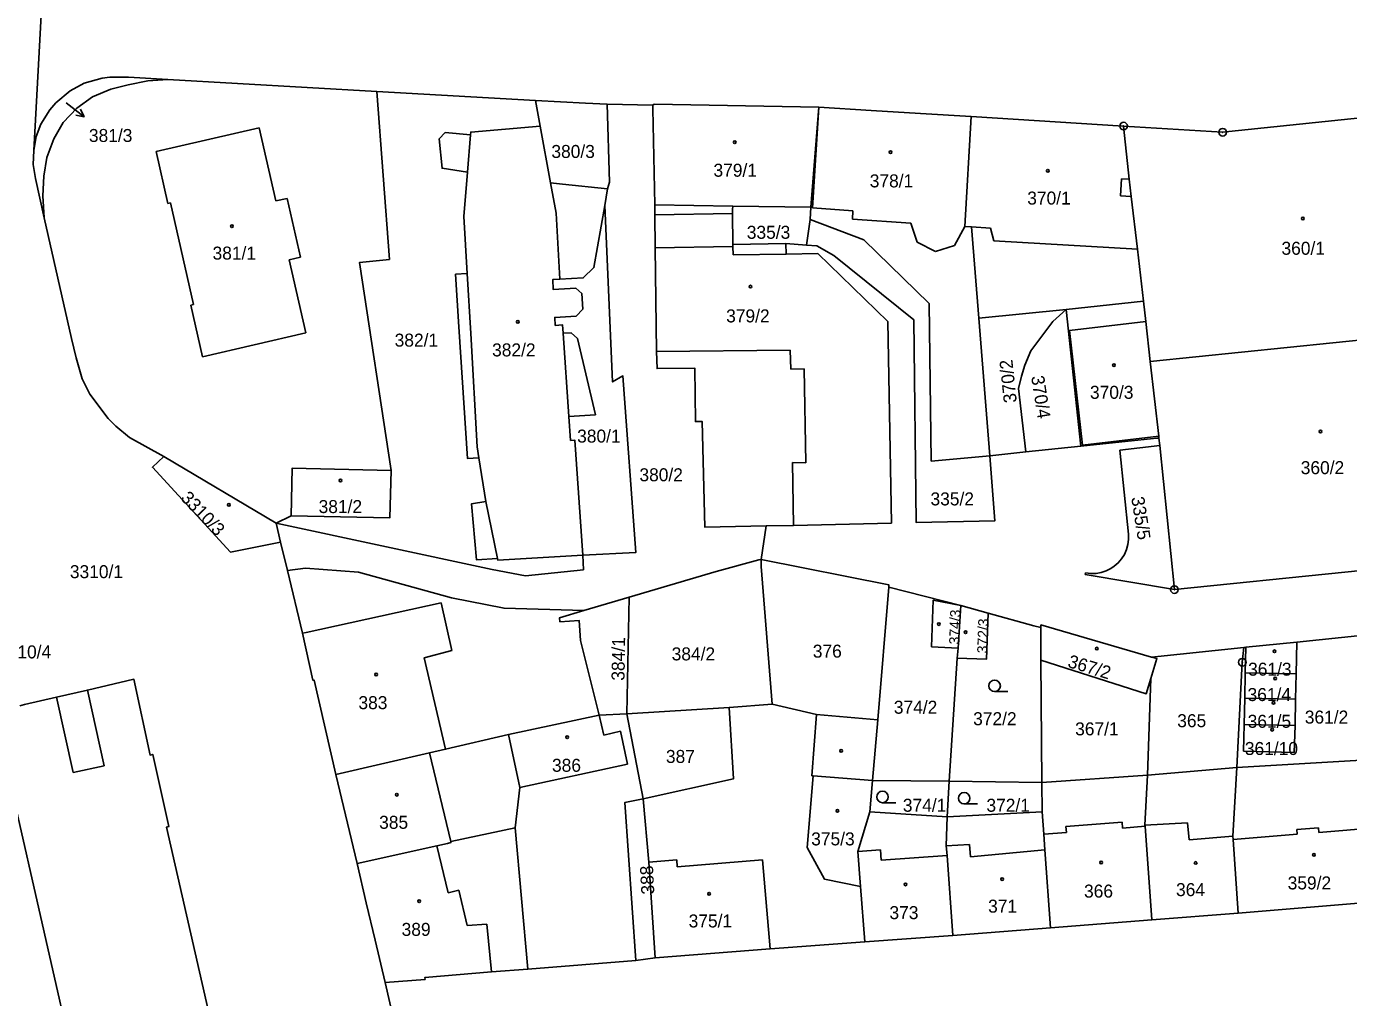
# Model space of a CAD drawing. Extents: x -733394 to -722299, y -1082822 to -1075049.
# Drawn here: x -728810.6 to -728637.6, y -1079423 to -1079295.9 of the extents above; entities that cross this region are included whole.
import ezdxf

# ---------------------------------------------------------------- set-up
doc = ezdxf.new("R2010")
doc.units = 0
for name, color, linetype in [('Hranice parcel', 7, 'Continuous'), ('Parcelní čísla', 7, 'Continuous'), ('Pop  PČ popisy', 7, 'Continuous'), ('Vnitřní kresba', 7, 'Continuous'), ('Značky bodu BP', 7, 'Continuous'), ('Značky budov', 7, 'Continuous'), ('Značky kultur', 7, 'Continuous')]:
    doc.layers.add(name, color=color, linetype=linetype)

msp = doc.modelspace()

# ---------------------------------------------------------------- linework, layer by layer
at = {"layer": 'Hranice parcel'}
for p, q in [((-728808.04, -1079282.72), (-728809.66, -1079312.11)), ((-728764.77, -1079304.39), (-728792.13, -1079302.84)), ((-728744.02, -1079305.57), (-728764.77, -1079304.39)), ((-728743.4, -1079308.95), (-728744.02, -1079305.57)), ((-728728.64, -1079306.19), (-728734.61, -1079306.05)), ((-728706.94, -1079306.46), (-728707.99, -1079319.55)), ((-728667.05, -1079308.93), (-728686.99, -1079307.69)), ((-728734.56, -1079317.13), (-728734.92, -1079319.33)), ((-728728.4, -1079319.25), (-728718.19, -1079319.41)), ((-728707.99, -1079319.55), (-728718.19, -1079319.41)), ((-728708.05, -1079321.14), (-728708.55, -1079324.51)), ((-728708.05, -1079321.14), (-728707.99, -1079319.55)), ((-728708.55, -1079324.51), (-728711.23, -1079324.31)), ((-728685.98, -1079334.08), (-728674.55, -1079332.94)), ((-728674.55, -1079332.94), (-728664.45, -1079331.86)), ((-728674.55, -1079332.94), (-728672.62, -1079350.8)), ((-728685.98, -1079334.08), (-728684.56, -1079352.08)), ((-728663.56, -1079339.73), (-728618.85, -1079335.2)), ((-728662.32, -1079350.72), (-728662.42, -1079349.75)), ((-728792.64, -1079352.18), (-728777.92, -1079360.9)), ((-728679.82, -1079351.54), (-728684.56, -1079352.08)), ((-728672.62, -1079350.8), (-728679.82, -1079351.54)), ((-728662.32, -1079350.72), (-728660.39, -1079369.59)), ((-728777.92, -1079360.9), (-728775.98, -1079359.93)), ((-728777.92, -1079360.9), (-728777.39, -1079363.36)), ((-728713.81, -1079361.26), (-728714.46, -1079365.65)), ((-728777.39, -1079363.36), (-728776.44, -1079367.09)), ((-728697.78, -1079369.26), (-728699.2, -1079386.62)), ((-728697.78, -1079369.26), (-728688.35, -1079371.68)), ((-728737.67, -1079372.33), (-728731.76, -1079370.58)), ((-728732.03, -1079385.83), (-728731.76, -1079370.58)), ((-728688.35, -1079371.68), (-728688.71, -1079377.25)), ((-728688.35, -1079371.68), (-728684.77, -1079372.66)), ((-728677.85, -1079378.84), (-728677.88, -1079374.54)), ((-728651.03, -1079377.14), (-728644.36, -1079376.45)), ((-728644.36, -1079376.45), (-728644.46, -1079380.63)), ((-728644.36, -1079376.45), (-728635.6, -1079375.55)), ((-728688.8, -1079378.56), (-728688.71, -1079377.25)), ((-728663.37, -1079378.41), (-728651.31, -1079377.17)), ((-728651.31, -1079377.17), (-728651.03, -1079377.14)), ((-728651.12, -1079380.48), (-728651.03, -1079377.14)), ((-728688.8, -1079378.56), (-728689.85, -1079394.67)), ((-728677.73, -1079394.81), (-728677.85, -1079378.84)), ((-728663.47, -1079381.21), (-728663.9, -1079393.89)), ((-728651.19, -1079383.78), (-728651.12, -1079380.48)), ((-728651.12, -1079380.48), (-728644.46, -1079380.63)), ((-728644.46, -1079380.63), (-728644.53, -1079383.93)), ((-728732.03, -1079385.83), (-728718.64, -1079385.03)), ((-728713.04, -1079384.6), (-728718.64, -1079385.03)), ((-728651.27, -1079387.23), (-728651.19, -1079383.78)), ((-728651.19, -1079383.78), (-728644.53, -1079383.93)), ((-728644.53, -1079383.93), (-728644.61, -1079387.38)), ((-728747.54, -1079388.54), (-728735.68, -1079386.04)), ((-728735.68, -1079386.04), (-728732.03, -1079385.83)), ((-728729.91, -1079396.97), (-728732.03, -1079385.83)), ((-728699.2, -1079386.62), (-728699.88, -1079394.56)), ((-728651.27, -1079387.23), (-728644.61, -1079387.38)), ((-728632.81, -1079391.73), (-728652.24, -1079392.85)), ((-728770.11, -1079393.77), (-728767.35, -1079405.43)), ((-728652.24, -1079392.85), (-728663.9, -1079393.89)), ((-728699.88, -1079394.56), (-728700.24, -1079398.67)), ((-728689.85, -1079394.67), (-728699.88, -1079394.56)), ((-728689.85, -1079394.67), (-728690.15, -1079399.32)), ((-728677.73, -1079394.81), (-728689.85, -1079394.67)), ((-728663.9, -1079393.89), (-728677.73, -1079394.81)), ((-728677.73, -1079394.81), (-728677.7, -1079398.66)), ((-728690.15, -1079399.32), (-728700.24, -1079398.67)), ((-728677.7, -1079398.66), (-728690.15, -1079399.32)), ((-728746.65, -1079400.77), (-728745, -1079419.27)), ((-728701.46, -1079408.46), (-728700.92, -1079415.69)), ((-728652.04, -1079411.93), (-728632.27, -1079410.29)), ((-728676.62, -1079413.85), (-728663.35, -1079412.79)), ((-728663.35, -1079412.79), (-728652.04, -1079411.93)), ((-728689.4, -1079414.85), (-728676.62, -1079413.85)), ((-728700.92, -1079415.69), (-728689.4, -1079414.85)), ((-728730.89, -1079418.14), (-728728.35, -1079417.78)), ((-728745, -1079419.27), (-728730.89, -1079418.14)), ((-728761.31, -1079431.12), (-728763.68, -1079421.02))]:
    msp.add_line(p, q, dxfattribs=at)
for points in [[(-728809.66, -1079312.11), (-728809.35, -1079310.3), (-728808.71, -1079308.66), (-728807.56, -1079306.79), (-728806.75, -1079305.87), (-728804.9, -1079304.3), (-728803.05, -1079303.33), (-728800.71, -1079302.66), (-728799.7, -1079302.55), (-728797.27, -1079302.55), (-728792.13, -1079302.84)], [(-728792.13, -1079302.84), (-728794.72, -1079303.01), (-728797.32, -1079303.54), (-728799.58, -1079304.08), (-728801.99, -1079305.09), (-728804.04, -1079306.57), (-728805.83, -1079308.45), (-728807.02, -1079310.58), (-728807.95, -1079313.04), (-728808.34, -1079315.47), (-728808.45, -1079318.07), (-728808.28, -1079320.95)], [(-728762.9, -1079354), (-728767.03, -1079326.77), (-728763.12, -1079326.37), (-728764.77, -1079304.39)], [(-728744.02, -1079305.57), (-728737.45, -1079305.94), (-728734.61, -1079306.05)], [(-728734.61, -1079306.05), (-728734.33, -1079316.27), (-728734.56, -1079317.13)], [(-728706.94, -1079306.46), (-728728.47, -1079306.06), (-728728.64, -1079306.19)], [(-728728.64, -1079306.19), (-728728.63, -1079306.69), (-728728.4, -1079319.25)], [(-728686.99, -1079307.69), (-728693.62, -1079307.28), (-728700.07, -1079306.9), (-728706.94, -1079306.46)], [(-728621.79, -1079306.38), (-728654.08, -1079309.73), (-728667.05, -1079308.93)], [(-728737.82, -1079365.08), (-728748.95, -1079365.72), (-728748.99, -1079365.52), (-728751.74, -1079365.68), (-728752.36, -1079358.36), (-728750.48, -1079358.05), (-728751.4, -1079352.35), (-728752.9, -1079352.41), (-728754.05, -1079335.2), (-728754.46, -1079328.32), (-728752.94, -1079328.23), (-728753.38, -1079320.78), (-728752.91, -1079314.97), (-728756.22, -1079314.45), (-728756.59, -1079310.62), (-728755.83, -1079309.79), (-728752.51, -1079310.06), (-728752.48, -1079309.71), (-728743.4, -1079308.95)], [(-728734.56, -1079317.13), (-728740.48, -1079316.53), (-728742.03, -1079316.37), (-728743.4, -1079308.95)], [(-728686.99, -1079307.69), (-728687.83, -1079322.08), (-728686.93, -1079322.13), (-728685.98, -1079334.08)], [(-728667.05, -1079308.93), (-728666.3, -1079315.88), (-728666.05, -1079318.14), (-728665.22, -1079325.05), (-728664.45, -1079331.86)], [(-728808.28, -1079320.95), (-728809.45, -1079315.79), (-728809.75, -1079313.95), (-728809.66, -1079312.11)], [(-728734.92, -1079319.33), (-728736.35, -1079327.44), (-728737.76, -1079328.79), (-728740.8, -1079328.97), (-728741.75, -1079329.02), (-728741.68, -1079330.32), (-728738.73, -1079330.15), (-728737.94, -1079330.86), (-728737.82, -1079332.9), (-728738.67, -1079333.8), (-728741.47, -1079333.97), (-728741.41, -1079335.01), (-728740.46, -1079334.96), (-728740.38, -1079336.05), (-728739.34, -1079335.98), (-728738.52, -1079336.71), (-728736.15, -1079346.71), (-728739.63, -1079346.95), (-728739.41, -1079350.06), (-728738.87, -1079350.03), (-728737.82, -1079365.08)], [(-728737.82, -1079365.08), (-728730.87, -1079364.75), (-728732.55, -1079341.62), (-728733.92, -1079342.42), (-728734.92, -1079319.33)], [(-728728.4, -1079319.25), (-728728.39, -1079320.05), (-728728.38, -1079320.55), (-728728.33, -1079324.85), (-728728.15, -1079338.43), (-728728.08, -1079340.67), (-728723.17, -1079340.6), (-728723.08, -1079347.6), (-728722.17, -1079347.6), (-728721.84, -1079361.42), (-728713.81, -1079361.26)], [(-728718.19, -1079319.41), (-728718.22, -1079319.86), (-728718.21, -1079320.38), (-728718.16, -1079324.43), (-728711.23, -1079324.31)], [(-728808.28, -1079320.95), (-728804.7, -1079336.74), (-728804.1, -1079339.24), (-728803.31, -1079342.01), (-728802.34, -1079344.02), (-728799.93, -1079347.21), (-728798.9, -1079348.19), (-728797.12, -1079349.67), (-728792.64, -1079352.18)], [(-728684.56, -1079352.08), (-728692.22, -1079352.78), (-728692.49, -1079332.13), (-728701.05, -1079323.81), (-728708.05, -1079321.14)], [(-728711.23, -1079324.31), (-728711.19, -1079325.71), (-728707.04, -1079325.62), (-728697.9, -1079334.5), (-728697.42, -1079360.89), (-728710.23, -1079361.19), (-728713.81, -1079361.26)], [(-728684.56, -1079352.08), (-728683.89, -1079360.57), (-728694.17, -1079360.81), (-728694.51, -1079334.27), (-728704.97, -1079325.85), (-728707.2, -1079324.61), (-728708.55, -1079324.51)], [(-728679.82, -1079351.54), (-728680.79, -1079343.29), (-728680.42, -1079341.67), (-728679.97, -1079340.23), (-728679.2, -1079338.35), (-728676.29, -1079334.49), (-728674.55, -1079332.94)], [(-728664.45, -1079331.86), (-728664.15, -1079334.51), (-728663.56, -1079339.73)], [(-728663.56, -1079339.73), (-728662.45, -1079349.49), (-728662.42, -1079349.75)], [(-728617.84, -1079345.18), (-728615.82, -1079365.03), (-728660.39, -1079369.59)], [(-728662.42, -1079349.75), (-728662.69, -1079349.78), (-728672.62, -1079350.8)], [(-728777.39, -1079363.36), (-728783.93, -1079364.68), (-728794.14, -1079353.57), (-728792.64, -1079352.18)], [(-728666.41, -1079362.32), (-728667.53, -1079351.36), (-728662.32, -1079350.72)], [(-728775.98, -1079359.93), (-728775.84, -1079353.69), (-728762.9, -1079354)], [(-728775.98, -1079359.93), (-728763.08, -1079360.2), (-728762.9, -1079354)], [(-728737.82, -1079365.08), (-728737.73, -1079367), (-728745.31, -1079367.77), (-728749.69, -1079366.95), (-728777.92, -1079360.9)], [(-728672.01, -1079367.41), (-728671.33, -1079367.49), (-728670.64, -1079367.47), (-728669.97, -1079367.36), (-728669.31, -1079367.14), (-728668.7, -1079366.84), (-728668.26, -1079366.54), (-728667.74, -1079366.09), (-728667.3, -1079365.56), (-728666.93, -1079364.98), (-728666.66, -1079364.35), (-728666.48, -1079363.69), (-728666.39, -1079363.01), (-728666.41, -1079362.32)], [(-728731.76, -1079370.58), (-728720.37, -1079367.21), (-728714.79, -1079365.69), (-728714.46, -1079365.65)], [(-728714.46, -1079365.65), (-728714.48, -1079366.58), (-728713.04, -1079384.6)], [(-728714.46, -1079365.65), (-728697.76, -1079368.98), (-728697.78, -1079369.26)], [(-728776.44, -1079367.09), (-728774.09, -1079366.79), (-728767.15, -1079367.32), (-728755.01, -1079370.68), (-728748.11, -1079372.03), (-728737.67, -1079372.33)], [(-728776.44, -1079367.09), (-728774.49, -1079375.3), (-728773.12, -1079381.46), (-728772.97, -1079381.42), (-728770.11, -1079393.77)], [(-728660.39, -1079369.59), (-728672.05, -1079367.59), (-728672.01, -1079367.41)], [(-728688.71, -1079377.25), (-728692.17, -1079377.06), (-728691.94, -1079370.96), (-728688.35, -1079371.68)], [(-728735.68, -1079386.04), (-728738.12, -1079376.24), (-728738.28, -1079373.64), (-728740.81, -1079373.79), (-728740.84, -1079373.28), (-728737.67, -1079372.33)], [(-728684.77, -1079372.66), (-728685, -1079378.71), (-728688.8, -1079378.56)], [(-728684.77, -1079372.66), (-728678.77, -1079374.34), (-728677.88, -1079374.54)], [(-728677.88, -1079374.54), (-728677.86, -1079374.21), (-728663.37, -1079378.41)], [(-728651.31, -1079377.17), (-728651.51, -1079379.09), (-728652.24, -1079392.85)], [(-728663.47, -1079381.21), (-728664.07, -1079383.22), (-728677.85, -1079378.84)], [(-728663.37, -1079378.41), (-728662.69, -1079378.62), (-728663.47, -1079381.21)], [(-728811.48, -1079384.78), (-728810.87, -1079384.64), (-728806.7, -1079383.67), (-728802.64, -1079382.73), (-728796.56, -1079381.33), (-728794.43, -1079391.25), (-728794.08, -1079391.15), (-728791.96, -1079400.58), (-728792.3, -1079400.68), (-728786.5, -1079426.09), (-728786.16, -1079426), (-728784.04, -1079435.36), (-728784.77, -1079435.57), (-728783.29, -1079442.14), (-728782.22, -1079441.95), (-728780.82, -1079448.13), (-728782.06, -1079448.35), (-728779.11, -1079461.33), (-728777.84, -1079461.1), (-728776.45, -1079467.29)], [(-728718.64, -1079385.03), (-728718.08, -1079394.34), (-728729.91, -1079396.97)], [(-728699.2, -1079386.62), (-728707.21, -1079385.94), (-728713.04, -1079384.6)], [(-728814.87, -1079385.56), (-728812.63, -1079395.4), (-728795.36, -1079471.49), (-728794.16, -1079476.76), (-728790.7, -1079475.99), (-728791.89, -1079470.72), (-728779.32, -1079467.93)], [(-728770.11, -1079393.77), (-728757.86, -1079390.95), (-728755.76, -1079390.47), (-728747.54, -1079388.54)], [(-728746.65, -1079400.77), (-728746.07, -1079395.47), (-728747.54, -1079388.54)], [(-728644.61, -1079387.38), (-728644.7, -1079390.89), (-728651.35, -1079390.73), (-728651.27, -1079387.23)], [(-728652.24, -1079392.85), (-728652.74, -1079401.84), (-728652.71, -1079402.29), (-728652.04, -1079411.93)], [(-728701.46, -1079408.46), (-728706.19, -1079407.48), (-728708.45, -1079403.34), (-728707.68, -1079393.95), (-728699.88, -1079394.56)], [(-728663.9, -1079393.89), (-728664.25, -1079400.42), (-728664.24, -1079400.56), (-728663.35, -1079412.79)], [(-728730.89, -1079418.14), (-728732.33, -1079397.45), (-728729.91, -1079396.97)], [(-728729.91, -1079396.97), (-728729.18, -1079405.24), (-728728.35, -1079417.78)], [(-728700.24, -1079398.67), (-728701.8, -1079403.87), (-728701.46, -1079408.46)], [(-728677.7, -1079398.66), (-728677.47, -1079401.61), (-728677.33, -1079403.64), (-728676.62, -1079413.85)], [(-728767.35, -1079405.43), (-728756.91, -1079403.11), (-728755.51, -1079402.8), (-728755.06, -1079402.7), (-728755.1, -1079402.53), (-728746.65, -1079400.77)], [(-728690.15, -1079399.32), (-728690.24, -1079403.11), (-728690.15, -1079404.37), (-728689.4, -1079414.85)], [(-728767.35, -1079405.43), (-728766.15, -1079410.56), (-728765, -1079415.47), (-728763.68, -1079421.02)], [(-728728.35, -1079417.78), (-728713.29, -1079416.61), (-728700.92, -1079415.69)], [(-728763.68, -1079421.02), (-728758.44, -1079420.61), (-728758.46, -1079420.33), (-728749.75, -1079419.6), (-728745, -1079419.27)]]:
    msp.add_lwpolyline(points, dxfattribs=at)
at = {"layer": 'Pop  PČ popisy'}
for p, q in [((-728805.4, -1079305.87), (-728803.04, -1079307.72)), ((-728803.04, -1079307.72), (-728803.52, -1079306.71)), ((-728803.04, -1079307.72), (-728804.13, -1079307.5))]:
    msp.add_line(p, q, dxfattribs=at)
at = {"layer": 'Vnitřní kresba'}
for p, q in [((-728706.94, -1079306.46), (-728707.75, -1079319.63)), ((-728793.64, -1079312.25), (-728780.15, -1079309.14)), ((-728780.15, -1079309.14), (-728777.97, -1079318.72)), ((-728752.91, -1079314.97), (-728752.51, -1079310.06)), ((-728793.64, -1079312.25), (-728792.11, -1079319.04)), ((-728667.33, -1079315.82), (-728667.46, -1079318.04)), ((-728666.3, -1079315.88), (-728667.33, -1079315.82)), ((-728742.03, -1079316.37), (-728741.3, -1079320.32)), ((-728792.11, -1079319.04), (-728791.77, -1079318.96)), ((-728791.77, -1079318.96), (-728788.77, -1079332.27)), ((-728777.97, -1079318.72), (-728776.5, -1079318.39)), ((-728776.5, -1079318.39), (-728774.75, -1079326.09)), ((-728667.46, -1079318.04), (-728666.05, -1079318.14)), ((-728741.3, -1079320.32), (-728740.8, -1079328.97)), ((-728728.38, -1079320.55), (-728718.21, -1079320.38)), ((-728707.75, -1079319.63), (-728702.46, -1079320.01)), ((-728702.46, -1079320.01), (-728702.52, -1079321.1)), ((-728702.52, -1079321.1), (-728694.9, -1079321.63)), ((-728694.9, -1079321.63), (-728694.06, -1079324.14)), ((-728689.16, -1079324.54), (-728687.83, -1079322.08)), ((-728686.93, -1079322.13), (-728684.44, -1079322.27)), ((-728684.44, -1079322.27), (-728684.01, -1079323.95)), ((-728718.16, -1079324.43), (-728718.16, -1079324.71)), ((-728694.06, -1079324.14), (-728691.67, -1079325.35)), ((-728691.67, -1079325.35), (-728689.16, -1079324.54)), ((-728684.01, -1079323.95), (-728665.22, -1079325.05)), ((-728774.75, -1079326.09), (-728776.22, -1079326.43)), ((-728728.33, -1079324.85), (-728718.16, -1079324.71)), ((-728718.16, -1079324.71), (-728718.15, -1079325.8)), ((-728718.15, -1079325.8), (-728711.19, -1079325.71)), ((-728776.22, -1079326.43), (-728774.05, -1079335.98)), ((-728752.94, -1079328.23), (-728752.47, -1079336.07)), ((-728788.77, -1079332.27), (-728789.12, -1079332.35)), ((-728789.12, -1079332.35), (-728787.59, -1079339.13)), ((-728664.15, -1079334.51), (-728674.13, -1079335.67)), ((-728774.05, -1079335.98), (-728787.59, -1079339.13)), ((-728752.47, -1079336.07), (-728751.64, -1079350.9)), ((-728740.38, -1079336.05), (-728739.63, -1079346.95)), ((-728674.13, -1079335.67), (-728672.4, -1079350.7)), ((-728728.15, -1079338.43), (-728710.68, -1079338.24)), ((-728710.68, -1079338.24), (-728710.6, -1079340.76)), ((-728710.6, -1079340.76), (-728708.84, -1079340.71)), ((-728708.84, -1079340.71), (-728708.61, -1079352.98)), ((-728672.4, -1079350.7), (-728662.45, -1079349.49)), ((-728751.64, -1079350.9), (-728751.4, -1079352.35)), ((-728710.38, -1079352.97), (-728708.61, -1079352.98)), ((-728710.38, -1079352.97), (-728710.23, -1079361.19)), ((-728750.48, -1079358.05), (-728748.99, -1079365.52)), ((-728774, -1079375.19), (-728756.34, -1079371.32)), ((-728756.34, -1079371.32), (-728754.97, -1079377.54)), ((-728774.49, -1079375.3), (-728774, -1079375.19)), ((-728754.97, -1079377.54), (-728758.57, -1079378.53)), ((-728758.57, -1079378.53), (-728755.76, -1079390.47)), ((-728802.64, -1079382.73), (-728800.46, -1079392.63)), ((-728806.7, -1079383.67), (-728804.49, -1079393.54)), ((-728735.68, -1079386.04), (-728735.07, -1079388.64)), ((-728707.21, -1079385.94), (-728707.85, -1079393.94)), ((-728735.07, -1079388.64), (-728732.89, -1079388.13)), ((-728731.97, -1079392.42), (-728732.89, -1079388.13)), ((-728757.86, -1079390.95), (-728755.1, -1079402.53)), ((-728804.49, -1079393.54), (-728800.46, -1079392.63)), ((-728746.07, -1079395.47), (-728731.97, -1079392.42)), ((-728707.68, -1079393.95), (-728707.85, -1079393.94)), ((-728674.59, -1079400.6), (-728667.25, -1079400.02)), ((-728674.53, -1079401.38), (-728674.59, -1079400.6)), ((-728667.25, -1079400.02), (-728667.19, -1079400.79)), ((-728667.19, -1079400.79), (-728664.24, -1079400.56)), ((-728664.25, -1079400.42), (-728658.69, -1079400.09)), ((-728658.48, -1079402.33), (-728658.69, -1079400.09)), ((-728644.39, -1079401), (-728641.53, -1079400.77)), ((-728641.53, -1079400.77), (-728641.48, -1079401.37)), ((-728641.48, -1079401.37), (-728633.01, -1079400.67)), ((-728674.53, -1079401.38), (-728677.47, -1079401.61)), ((-728658.48, -1079402.33), (-728652.74, -1079401.84)), ((-728652.71, -1079402.29), (-728644.34, -1079401.6)), ((-728644.34, -1079401.6), (-728644.39, -1079401)), ((-728756.91, -1079403.11), (-728755.44, -1079409.27)), ((-728698.85, -1079403.65), (-728701.8, -1079403.87)), ((-728698.75, -1079405.01), (-728698.85, -1079403.65)), ((-728690.24, -1079403.11), (-728687.2, -1079402.93)), ((-728687.2, -1079402.93), (-728687.07, -1079404.54)), ((-728687.07, -1079404.54), (-728677.33, -1079403.64)), ((-728729.18, -1079405.24), (-728725.51, -1079404.94)), ((-728725.51, -1079404.94), (-728725.44, -1079405.87)), ((-728725.44, -1079405.87), (-728714.28, -1079404.97)), ((-728714.28, -1079404.97), (-728713.29, -1079416.61)), ((-728698.75, -1079405.01), (-728690.15, -1079404.37)), ((-728755.44, -1079409.27), (-728754.04, -1079408.94)), ((-728754.04, -1079408.94), (-728752.93, -1079413.56)), ((-728752.93, -1079413.56), (-728750.38, -1079413.35)), ((-728750.38, -1079413.35), (-728749.75, -1079419.6))]:
    msp.add_line(p, q, dxfattribs=at)
at = {"layer": 'Značky bodu BP'}
for centre, radius in [((-728667.05, -1079308.93), 0.5), ((-728667.05, -1079308.93), 0.0303), ((-728654.08, -1079309.73), 0.5), ((-728654.08, -1079309.73), 0.0303), ((-728660.39, -1079369.59), 0.5), ((-728660.39, -1079369.59), 0.0303), ((-728651.51, -1079379.09), 0.5), ((-728651.51, -1079379.09), 0.0303)]:
    msp.add_circle(centre, radius, dxfattribs=at)
at = {"layer": 'Značky budov'}
for centre in [(-728717.93, -1079311.04), (-728697.53, -1079312.34), (-728676.96, -1079314.78), (-728643.58, -1079321.03), (-728783.72, -1079322.03), (-728715.87, -1079329.94), (-728746.32, -1079334.56), (-728668.3, -1079340.21), (-728641.27, -1079348.91), (-728769.53, -1079355.3), (-728784.12, -1079358.5), (-728691.21, -1079374.09), (-728687.71, -1079375.17), (-728670.54, -1079377.31), (-728647.28, -1079377.66), (-728764.86, -1079380.69), (-728647.21, -1079381.22), (-728647.43, -1079384.41), (-728647.59, -1079387.92), (-728739.85, -1079388.9), (-728704.01, -1079390.69), (-728762.14, -1079396.43), (-728704.5, -1079398.55), (-728642.13, -1079404.3), (-728669.99, -1079405.3), (-728657.61, -1079405.36), (-728682.93, -1079407.47), (-728721.29, -1079409.39), (-728695.57, -1079408.16), (-728759.23, -1079410.36)]:
    msp.add_circle(centre, 0.175, dxfattribs=at)
at = {"layer": 'Značky kultur'}
for p, q in [((-728683.92, -1079382.93), (-728682.17, -1079382.93)), ((-728698.59, -1079397.47), (-728696.84, -1079397.47)), ((-728687.91, -1079397.64), (-728686.16, -1079397.64))]:
    msp.add_line(p, q, dxfattribs=at)
for centre in [(-728683.92, -1079382.18), (-728698.59, -1079396.72), (-728687.91, -1079396.89)]:
    msp.add_circle(centre, 0.75, dxfattribs=at)

# ---------------------------------------------------------------- texts
at = {"layer": 'Parcelní čísla'}
for s, p in [('381/3', (-728802.44, -1079311.01)), ('380/3', (-728741.92, -1079313.1)), ('379/1', (-728720.71, -1079315.56)), ('378/1', (-728700.26, -1079316.95)), ('370/1', (-728679.65, -1079319.2)), ('335/3', (-728716.35, -1079323.68)), ('381/1', (-728786.26, -1079326.4)), ('360/1', (-728646.38, -1079325.77)), ('379/2', (-728719.05, -1079334.62)), ('382/1', (-728762.43, -1079337.79)), ('382/2', (-728749.68, -1079339.07)), ('370/3', (-728671.44, -1079344.62)), ('380/1', (-728738.55, -1079350.35)), ('380/2', (-728730.4, -1079355.41)), ('360/2', (-728643.86, -1079354.48)), ('335/2', (-728692.31, -1079358.57)), ('381/2', (-728772.38, -1079359.57)), ('3310/1', (-728804.93, -1079368.09)), ('3310/4', (-728814.33, -1079378.59)), ('384/2', (-728726.18, -1079378.85)), ('376', (-728707.71, -1079378.49)), ('361/3', (-728650.75, -1079380.85)), ('361/4', (-728650.82, -1079384.17)), ('383', (-728767.17, -1079385.23)), ('374/2', (-728697.11, -1079385.83)), ('372/2', (-728686.73, -1079387.33)), ('367/1', (-728673.38, -1079388.66)), ('365', (-728660.02, -1079387.59)), ('361/5', (-728650.81, -1079387.67)), ('361/2', (-728643.33, -1079387.12)), ('361/10', (-728651.17, -1079391.23)), ('386', (-728741.84, -1079393.43)), ('387', (-728726.93, -1079392.27)), ('374/1', (-728695.93, -1079398.66)), ('372/1', (-728684.99, -1079398.66)), ('385', (-728764.46, -1079400.89)), ('375/3', (-728707.92, -1079403.06)), ('359/2', (-728645.57, -1079408.82)), ('366', (-728672.22, -1079409.89)), ('364', (-728660.18, -1079409.7)), ('373', (-728697.68, -1079412.71)), ('371', (-728684.77, -1079411.86)), ('375/1', (-728723.96, -1079413.8)), ('389', (-728761.52, -1079414.9))]:
    msp.add_text(s, height=1.7, dxfattribs=at).set_placement(p)
for s, height, rotation, p in [('370/2', 1.7, 96, (-728681.01, -1079345.07)), ('370/4', 1.7, 279, (-728679.15, -1079341.71)), ('3310/3', 1.7, 314, (-728790.54, -1079357.7)), ('335/5', 1.7, 279, (-728666.05, -1079357.55)), ('374/3', 1.36, 88, (-728688.52, -1079376.78)), ('372/3', 1.36, 88, (-728684.85, -1079377.95)), ('384/1', 1.7, 89, (-728732.36, -1079381.52)), ('367/2', 1.7, 343, (-728674.46, -1079379.69)), ('388', 1.7, 93, (-728728.44, -1079409.44))]:
    msp.add_text(s, height=height, rotation=rotation, dxfattribs=at).set_placement(p)

doc.saveas('drawing.dxf')
